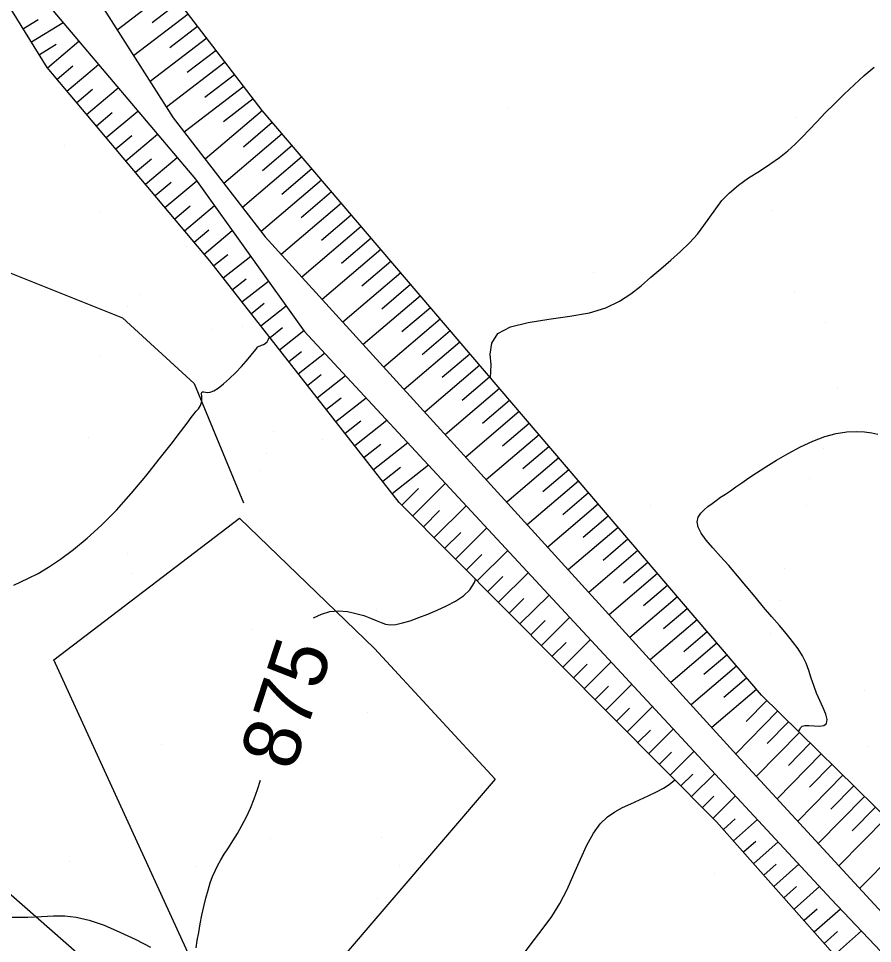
# Model space of a CAD drawing. Extents: x 400243 to 403697, y 4403637 to 4408083.
# Drawn here: x 402808 to 402920.2, y 4406336.6 to 4406458.2 of the extents above; entities that cross this region are included whole.
import ezdxf

# ---------------------------------------------------------------- set-up
doc = ezdxf.new("R2010")
doc.units = 0
doc.layers.add('HH_IC', color=7, linetype='Continuous')

msp = doc.modelspace()

# ---------------------------------------------------------------- linework, layer by layer
at = {"layer": 'HH_IC'}
for p, q in [((402840.01, 4406446.12), (402808.2, 4406487.63)), ((402811.77, 4406451.75), (402794.37, 4406479.94)), ((402808.28, 4406476.56), (402828.32, 4406445.14)), ((402809.29, 4406463.06), (402831.25, 4406437.09)), ((402827.85, 4406461.98), (402820.95, 4406456.69)), ((402825.55, 4406457.7), (402829.07, 4406460.39)), ((402830.29, 4406458.8), (402823.11, 4406453.31)), ((402810.58, 4406458.04), (402808.63, 4406456.84)), ((402809.68, 4406455.14), (402813.83, 4406457.7)), ((402827.85, 4406454.42), (402831.5, 4406457.22)), ((402812.93, 4406454.8), (402810.73, 4406453.44)), ((402811.78, 4406451.74), (402815.93, 4406455.22)), ((402832.72, 4406455.63), (402825.27, 4406449.92)), ((402830.14, 4406451.14), (402833.93, 4406454.04)), ((402814.35, 4406448.67), (402818.51, 4406452.16)), ((402835.15, 4406452.45), (402827.43, 4406446.54)), ((402811.77, 4406451.75), (402811.77, 4406451.75)), ((402833.1, 4406426.36), (402811.77, 4406451.75)), ((402815.14, 4406451.95), (402813.07, 4406450.21)), ((402832.45, 4406447.87), (402836.37, 4406450.87)), ((402817.72, 4406448.89), (402815.64, 4406447.14)), ((402816.93, 4406445.61), (402821.09, 4406449.11)), ((402837.58, 4406449.28), (402829.76, 4406443.28)), ((402828.13, 4406447.8), (402828.13, 4406447.8)), ((402834.89, 4406444.69), (402838.8, 4406447.69)), ((402819.5, 4406442.55), (402823.67, 4406446.05)), ((402840.02, 4406446.1), (402832.52, 4406439.71)), ((402840.01, 4406446.12), (402840.01, 4406446.12)), ((402905.56, 4406369.26), (402840.01, 4406446.12)), ((402872.17, 4406446.47), (402872.17, 4406446.47)), ((402820.3, 4406445.83), (402818.21, 4406444.08)), ((402828.32, 4406445.14), (402828.32, 4406445.14)), ((402828.32, 4406445.14), (402840.38, 4406429.52)), ((402910.22, 4406445.21), (402910.22, 4406445.21)), ((402837.53, 4406441.35), (402841.32, 4406444.58)), ((402822.88, 4406442.77), (402820.79, 4406441.02)), ((402822.07, 4406439.49), (402826.25, 4406443)), ((402842.61, 4406443.06), (402834.96, 4406436.54)), ((402814.08, 4406441.55), (402814.08, 4406441.55)), ((402840.05, 4406438.25), (402843.91, 4406441.54)), ((402845.21, 4406440.02), (402837.41, 4406433.37)), ((402825.45, 4406439.71), (402823.36, 4406437.96)), ((402824.65, 4406436.42), (402828.84, 4406439.95)), ((402842.57, 4406435.14), (402846.51, 4406438.5)), ((402828.03, 4406436.66), (402825.93, 4406434.89)), ((402827.22, 4406433.36), (402831.4, 4406436.88)), ((402831.25, 4406437.09), (402831.25, 4406437.09)), ((402831.25, 4406437.09), (402845.52, 4406417.11)), ((402847.8, 4406436.97), (402839.86, 4406430.2)), ((402845.13, 4406432.06), (402849.1, 4406435.45)), ((402829.98, 4406435.01), (402829.98, 4406435.01)), ((402850.4, 4406433.93), (402842.5, 4406427.19)), ((402818.57, 4406432.73), (402818.57, 4406432.73)), ((402830.54, 4406433.54), (402828.51, 4406431.83)), ((402829.79, 4406430.3), (402833.73, 4406433.61)), ((402906.83, 4406432.99), (402906.83, 4406432.99)), ((402847.77, 4406429.06), (402851.7, 4406432.41)), ((402832.99, 4406430.37), (402831.08, 4406428.77)), ((402832.37, 4406427.24), (402836.07, 4406430.35)), ((402853, 4406430.89), (402845.19, 4406424.23)), ((402840.38, 4406429.52), (402840.38, 4406429.52)), ((402840.38, 4406429.52), (402902.34, 4406361.38)), ((402850.41, 4406426.06), (402854.29, 4406429.37)), ((402830.08, 4406428.22), (402830.08, 4406428.22)), ((402855.59, 4406427.84), (402847.88, 4406421.27)), ((402835.48, 4406427.14), (402833.63, 4406425.69)), ((402834.86, 4406424.11), (402838.49, 4406426.96)), ((402802.71, 4406426.43), (402821.63, 4406418.88)), ((402833.1, 4406426.36), (402833.1, 4406426.36)), ((402857.99, 4406394.6), (402833.1, 4406426.36)), ((402853.06, 4406423.05), (402856.89, 4406426.32)), ((402858.19, 4406424.8), (402850.57, 4406418.31)), ((402883.51, 4406424.87), (402883.51, 4406424.87)), ((402837.88, 4406423.93), (402836.1, 4406422.54)), ((402837.33, 4406420.97), (402840.82, 4406423.7)), ((402855.7, 4406420.05), (402859.49, 4406423.28)), ((402823.83, 4406421.99), (402823.83, 4406421.99)), ((402860.78, 4406421.76), (402853.27, 4406415.35)), ((402909.94, 4406422.3), (402909.94, 4406422.3)), ((402840.27, 4406420.73), (402838.57, 4406419.39)), ((402822.3, 4406420.38), (402822.3, 4406420.38)), ((402839.8, 4406417.82), (402843.14, 4406420.44)), ((402858.35, 4406417.05), (402862.08, 4406420.23)), ((402821.63, 4406418.88), (402821.63, 4406418.88)), ((402821.63, 4406418.88), (402831.06, 4406410.25)), ((402863.38, 4406418.71), (402855.96, 4406412.39)), ((402913.96, 4406418.2), (402913.96, 4406418.2)), ((402833.5, 4406417.27), (402833.5, 4406417.27)), ((402837.46, 4406417.72), (402837.46, 4406417.72)), ((402842.67, 4406417.53), (402841.03, 4406416.24)), ((402842.27, 4406414.67), (402845.47, 4406417.18)), ((402845.52, 4406417.11), (402845.52, 4406417.11)), ((402845.52, 4406417.11), (402914.74, 4406342.46)), ((402860.99, 4406414.05), (402864.68, 4406417.19)), ((402865.97, 4406415.67), (402858.65, 4406409.43)), ((402818.57, 4406413.97), (402818.57, 4406413.97)), ((402845.16, 4406414.4), (402843.5, 4406413.09)), ((402844.73, 4406411.52), (402848.19, 4406414.23)), ((402863.64, 4406411.05), (402867.27, 4406414.15)), ((402868.57, 4406412.63), (402861.34, 4406406.46)), ((402847.76, 4406411.35), (402845.97, 4406409.95)), ((402847.2, 4406408.37), (402850.92, 4406411.29)), ((402866.28, 4406408.04), (402869.87, 4406411.1)), ((402831.06, 4406410.25), (402831.06, 4406410.25)), ((402831.06, 4406410.25), (402837.53, 4406394.53)), ((402871.17, 4406409.58), (402864.04, 4406403.5)), ((402915.61, 4406409.63), (402915.61, 4406409.63)), ((402849.67, 4406405.22), (402853.65, 4406408.34)), ((402850.36, 4406408.31), (402848.44, 4406406.8)), ((402868.92, 4406405.04), (402872.46, 4406408.06)), ((402831.16, 4406406.62), (402831.16, 4406406.62)), ((402873.76, 4406406.54), (402866.73, 4406400.54)), ((402852.96, 4406405.26), (402850.9, 4406403.65)), ((402852.14, 4406402.08), (402856.38, 4406405.4)), ((402871.57, 4406402.04), (402875.06, 4406405.02)), ((402841.52, 4406403.95), (402841.52, 4406403.95)), ((402876.36, 4406403.5), (402869.42, 4406397.58)), ((402817.17, 4406403.08), (402817.17, 4406403.08)), ((402847.94, 4406402.84), (402847.94, 4406402.84)), ((402854.6, 4406398.93), (402859.11, 4406402.46)), ((402855.56, 4406402.22), (402853.37, 4406400.5)), ((402874.21, 4406399.04), (402877.65, 4406401.97)), ((402913.76, 4406401.71), (402913.76, 4406401.71)), ((402840.56, 4406401.03), (402840.56, 4406401.03)), ((402878.95, 4406400.45), (402872.12, 4406394.62)), ((402839.82, 4406398.77), (402839.82, 4406398.77)), ((402858.16, 4406399.17), (402855.84, 4406397.35)), ((402857.07, 4406395.78), (402861.84, 4406399.52)), ((402876.86, 4406396.04), (402880.25, 4406398.93)), ((402881.55, 4406397.41), (402874.81, 4406391.66)), ((402911.88, 4406397.8), (402911.88, 4406397.8)), ((402860.53, 4406396.41), (402858.35, 4406394.24)), ((402859.76, 4406392.83), (402864.07, 4406397.11)), ((402879.5, 4406393.03), (402882.85, 4406395.89)), ((402837.53, 4406394.53), (402837.53, 4406394.53)), ((402857.99, 4406394.6), (402857.99, 4406394.6)), ((402899.67, 4406352.63), (402857.99, 4406394.6)), ((402862.58, 4406389.99), (402866.79, 4406394.17)), ((402884.14, 4406394.37), (402877.5, 4406388.7)), ((402890.97, 4406394.13), (402890.97, 4406394.13)), ((402911.46, 4406394.25), (402911.46, 4406394.25)), ((402863.3, 4406393.52), (402861.17, 4406391.41)), ((402882.14, 4406390.03), (402885.44, 4406392.84)), ((402812.62, 4406373.9), (402837.03, 4406392.51)), ((402837.03, 4406392.51), (402837.03, 4406392.51)), ((402837.03, 4406392.51), (402854.74, 4406375.41)), ((402886.74, 4406391.32), (402880.19, 4406385.74)), ((402866.07, 4406390.64), (402863.99, 4406388.57)), ((402865.4, 4406387.15), (402869.51, 4406391.24)), ((402884.79, 4406387.03), (402888.04, 4406389.8)), ((402822.33, 4406387.88), (402822.33, 4406387.88)), ((402868.84, 4406387.75), (402866.81, 4406385.73)), ((402868.21, 4406384.31), (402872.24, 4406388.3)), ((402889.33, 4406388.28), (402882.89, 4406382.78)), ((402887.43, 4406384.03), (402890.63, 4406386.76)), ((402822.85, 4406385.29), (402822.85, 4406385.29)), ((402871.03, 4406381.47), (402874.96, 4406385.37)), ((402891.93, 4406385.24), (402885.58, 4406379.82)), ((402908.55, 4406385.91), (402908.55, 4406385.91)), ((402871.61, 4406384.86), (402869.62, 4406382.89)), ((402890.08, 4406381.03), (402893.23, 4406383.71)), ((402874.38, 4406381.98), (402872.44, 4406380.05)), ((402873.85, 4406378.63), (402877.68, 4406382.43)), ((402894.53, 4406382.19), (402888.27, 4406376.86)), ((402907.98, 4406381.69), (402907.98, 4406381.69)), ((402855.03, 4406380.53), (402855.03, 4406380.53)), ((402892.72, 4406378.02), (402895.82, 4406380.67)), ((402876.67, 4406375.8), (402880.4, 4406379.5)), ((402838.62, 4406377.96), (402838.62, 4406377.96)), ((402877.15, 4406379.09), (402875.26, 4406377.21)), ((402897.12, 4406379.15), (402890.96, 4406373.9)), ((402895.37, 4406375.02), (402898.42, 4406377.63)), ((402906.77, 4406377.36), (402906.77, 4406377.36)), ((402879.92, 4406376.2), (402878.08, 4406374.38)), ((402879.49, 4406372.96), (402883.12, 4406376.56)), ((402899.72, 4406376.1), (402893.66, 4406370.94)), ((402854.74, 4406375.41), (402854.74, 4406375.41)), ((402854.74, 4406375.41), (402870.61, 4406358.24)), ((402898.01, 4406372.02), (402901.02, 4406374.58)), ((402812.62, 4406373.9), (402812.62, 4406373.9)), ((402832.11, 4406331.32), (402812.62, 4406373.9)), ((402882.69, 4406373.32), (402880.9, 4406371.54)), ((402882.31, 4406370.12), (402885.84, 4406373.63)), ((402902.31, 4406373.06), (402896.35, 4406367.98)), ((402885.12, 4406367.28), (402888.56, 4406370.69)), ((402900.65, 4406369.02), (402903.61, 4406371.54)), ((402885.46, 4406370.43), (402883.72, 4406368.7)), ((402904.91, 4406370.02), (402899.04, 4406365.01)), ((402919.07, 4406369.88), (402919.07, 4406369.88)), ((402903.56, 4406365.79), (402906.27, 4406368.56)), ((402905.56, 4406369.26), (402905.56, 4406369.26)), ((402937.32, 4406338.07), (402905.56, 4406369.26)), ((402888.23, 4406367.54), (402886.53, 4406365.86)), ((402887.94, 4406364.44), (402891.28, 4406367.76)), ((402907.7, 4406367.16), (402902.19, 4406361.55)), ((402853.89, 4406366.92), (402853.89, 4406366.92)), ((402839.8, 4406364.77), (402839.8, 4406364.77)), ((402891, 4406364.66), (402889.35, 4406363.02)), ((402890.76, 4406361.6), (402894.01, 4406364.82)), ((402906.34, 4406362.91), (402909.13, 4406365.75)), ((402910.55, 4406364.35), (402904.9, 4406358.6)), ((402826.81, 4406362.78), (402826.81, 4406362.78)), ((402909.12, 4406360.04), (402911.98, 4406362.95)), ((402919.53, 4406362.56), (402919.53, 4406362.56)), ((402893.77, 4406361.77), (402892.17, 4406360.18)), ((402893.58, 4406358.76), (402896.73, 4406361.89)), ((402902.34, 4406361.38), (402902.34, 4406361.38)), ((402902.34, 4406361.38), (402934.09, 4406326.86)), ((402913.41, 4406361.55), (402907.62, 4406355.65)), ((402911.9, 4406357.16), (402914.83, 4406360.15)), ((402896.54, 4406358.88), (402894.99, 4406357.35)), ((402896.4, 4406355.93), (402899.45, 4406358.95)), ((402916.26, 4406358.75), (402910.33, 4406352.7)), ((402817.62, 4406333.67), (402790.33, 4406357.62)), ((402870.61, 4406358.24), (402843.42, 4406326.49)), ((402870.61, 4406358.24), (402870.61, 4406358.24)), ((402914.69, 4406354.29), (402917.69, 4406357.35)), ((402899.31, 4406356), (402897.81, 4406354.51)), ((402899.22, 4406353.09), (402902.17, 4406356.02)), ((402919.12, 4406355.95), (402913.04, 4406349.76)), ((402917.47, 4406351.41), (402920.54, 4406354.54)), ((402899.67, 4406352.63), (402899.67, 4406352.63)), ((402933.83, 4406314.03), (402899.67, 4406352.63)), ((402902.13, 4406353), (402900.57, 4406351.61)), ((402901.89, 4406350.12), (402905.05, 4406352.91)), ((402921.97, 4406353.14), (402915.75, 4406346.81)), ((402915.34, 4406351.89), (402915.34, 4406351.89)), ((402841.09, 4406350.46), (402841.09, 4406350.46)), ((402855.69, 4406350.52), (402855.69, 4406350.52)), ((402904.82, 4406350.03), (402903.22, 4406348.62)), ((402904.55, 4406347.12), (402907.77, 4406349.98)), ((402924.82, 4406350.34), (402918.46, 4406343.86)), ((402814.7, 4406347.36), (402814.7, 4406347.36)), ((402831.36, 4406346.77), (402831.36, 4406346.77)), ((402858.07, 4406346.91), (402858.07, 4406346.91)), ((402907.5, 4406347.07), (402905.87, 4406345.62)), ((402907.2, 4406344.13), (402910.49, 4406347.04)), ((402860.59, 4406345.28), (402860.59, 4406345.28)), ((402899.38, 4406345.87), (402899.38, 4406345.87)), ((402910.19, 4406344.1), (402908.52, 4406342.63)), ((402909.85, 4406341.13), (402913.21, 4406344.11)), ((402855.19, 4406342.56), (402855.19, 4406342.56)), ((402914.74, 4406342.46), (402914.74, 4406342.46)), ((402914.74, 4406342.46), (402941.82, 4406313.88)), ((402912.87, 4406341.14), (402911.17, 4406339.63)), ((402912.5, 4406338.14), (402915.95, 4406341.19)), ((402915.57, 4406338.19), (402913.82, 4406336.64)), ((402915.15, 4406335.14), (402918.7, 4406338.28))]:
    msp.add_line(p, q, dxfattribs=at)
for points in [[(402870, 4406410.95), (402870.07, 4406412.69), (402869.95, 4406414.1), (402870.14, 4406415.54), (402870.96, 4406416.79), (402872.62, 4406417.67), (402874.94, 4406418.26), (402877.64, 4406418.69), (402880.41, 4406419.07), (402882.99, 4406419.54), (402885.14, 4406420.2), (402886.91, 4406421.04), (402888.41, 4406422.01), (402889.75, 4406423.08), (402891.03, 4406424.19), (402892.34, 4406425.32), (402893.65, 4406426.46), (402894.92, 4406427.6), (402896.1, 4406428.73), (402897.15, 4406429.87), (402898.02, 4406431), (402898.8, 4406432.11), (402899.56, 4406433.21), (402900.38, 4406434.28), (402901.36, 4406435.31), (402902.55, 4406436.3), (402903.89, 4406437.25), (402905.3, 4406438.16), (402906.68, 4406439.06), (402907.95, 4406439.93), (402909.05, 4406440.8), (402910.02, 4406441.68), (402910.93, 4406442.6), (402911.85, 4406443.58), (402912.83, 4406444.64), (402913.94, 4406445.79), (402915.15, 4406447.01), (402916.43, 4406448.26), (402917.74, 4406449.5), (402919.06, 4406450.7), (402920.36, 4406451.82)], [(402807.38, 4406383.74), (402808.27, 4406384.15), (402809.32, 4406384.65), (402810.55, 4406385.27), (402811.94, 4406386.09), (402813.5, 4406387.12), (402815.19, 4406388.39), (402817, 4406389.89), (402818.89, 4406391.63), (402820.84, 4406393.6), (402822.8, 4406395.79), (402824.71, 4406398.06), (402826.48, 4406400.27), (402828.02, 4406402.26), (402829.25, 4406403.88), (402830.12, 4406405.03), (402830.68, 4406405.76), (402831.01, 4406406.19), (402831.2, 4406406.43), (402831.33, 4406406.58), (402831.47, 4406406.74), (402831.62, 4406406.92), (402831.77, 4406407.12), (402831.9, 4406407.35), (402831.99, 4406407.6), (402832.05, 4406407.86), (402832.07, 4406408.13), (402832.06, 4406408.39), (402832.05, 4406408.63), (402832.03, 4406408.82), (402832.03, 4406408.97), (402832.05, 4406409.07), (402832.1, 4406409.13), (402832.19, 4406409.14), (402832.33, 4406409.12), (402832.53, 4406409.08), (402832.8, 4406409.06), (402833.17, 4406409.11), (402833.63, 4406409.29), (402834.22, 4406409.64), (402834.93, 4406410.2), (402835.71, 4406410.91), (402836.51, 4406411.7), (402837.26, 4406412.48), (402837.9, 4406413.18), (402838.38, 4406413.75), (402838.73, 4406414.18), (402838.98, 4406414.49), (402839.14, 4406414.72), (402839.27, 4406414.88), (402839.37, 4406415), (402839.48, 4406415.08), (402839.6, 4406415.14), (402839.74, 4406415.2), (402839.92, 4406415.27), (402840.15, 4406415.36), (402840.4, 4406415.49), (402840.64, 4406415.71), (402840.84, 4406416.04), (402840.94, 4406416.37)], [(402910.42, 4406364.48), (402910.6, 4406364.77), (402910.71, 4406364.98), (402910.9, 4406365.17), (402911.25, 4406365.27), (402911.81, 4406365.27), (402912.49, 4406365.23), (402913.18, 4406365.21), (402913.76, 4406365.29), (402914.12, 4406365.55), (402914.19, 4406366.05), (402914.01, 4406366.75), (402913.66, 4406367.6), (402913.23, 4406368.55), (402912.8, 4406369.54), (402912.44, 4406370.54), (402912.12, 4406371.52), (402911.8, 4406372.5), (402911.43, 4406373.46), (402910.97, 4406374.42), (402910.38, 4406375.36), (402909.67, 4406376.32), (402908.85, 4406377.33), (402907.94, 4406378.4), (402906.93, 4406379.57), (402905.86, 4406380.85), (402904.73, 4406382.21), (402903.58, 4406383.6), (402902.42, 4406384.97), (402901.27, 4406386.29), (402900.17, 4406387.51), (402899.17, 4406388.63), (402898.31, 4406389.64), (402897.66, 4406390.54), (402897.25, 4406391.34), (402897.14, 4406392.04), (402897.27, 4406392.64), (402897.59, 4406393.17), (402898.03, 4406393.64), (402898.55, 4406394.07), (402899.08, 4406394.47), (402899.63, 4406394.87), (402900.21, 4406395.27), (402900.83, 4406395.69), (402901.49, 4406396.14), (402902.2, 4406396.64), (402902.99, 4406397.19), (402903.9, 4406397.82), (402904.94, 4406398.51), (402906.15, 4406399.29), (402907.55, 4406400.15), (402909.08, 4406401.04), (402910.69, 4406401.89), (402912.32, 4406402.65), (402913.9, 4406403.25), (402915.4, 4406403.65), (402916.77, 4406403.86), (402918.01, 4406403.92), (402919.12, 4406403.86), (402920.06, 4406403.73), (402920.86, 4406403.56)], [(402846.73, 4406379.42), (402847.77, 4406379.92), (402848.88, 4406380.24), (402850.03, 4406380.34), (402851.19, 4406380.25), (402852.3, 4406380.02), (402853.33, 4406379.72), (402854.23, 4406379.38), (402854.97, 4406379.06), (402855.6, 4406378.8), (402856.2, 4406378.61), (402856.82, 4406378.52), (402857.55, 4406378.56), (402858.42, 4406378.75), (402859.43, 4406379.05), (402860.55, 4406379.46), (402861.74, 4406379.93), (402862.97, 4406380.45), (402864.2, 4406381), (402865.37, 4406381.61), (402866.42, 4406382.3), (402867.28, 4406383.11), (402867.89, 4406384.08), (402868.01, 4406384.52)], [(402831.32, 4406336.05), (402831.47, 4406337.02), (402831.65, 4406338.08), (402831.85, 4406339.2), (402832.07, 4406340.35), (402832.33, 4406341.49), (402832.6, 4406342.59), (402832.88, 4406343.64), (402833.17, 4406344.59), (402833.48, 4406345.43), (402833.8, 4406346.19), (402834.16, 4406346.9), (402834.56, 4406347.62), (402835.02, 4406348.38), (402835.55, 4406349.21), (402836.13, 4406350.12), (402836.74, 4406351.1), (402837.34, 4406352.14), (402837.92, 4406353.25), (402838.45, 4406354.42), (402838.94, 4406355.63), (402839.37, 4406356.85), (402839.77, 4406358.08)], [(402874.55, 4406335.54), (402875.75, 4406337.14), (402876.91, 4406338.65), (402878.03, 4406340.19), (402879.07, 4406341.86), (402880.03, 4406343.73), (402880.93, 4406345.73), (402881.79, 4406347.71), (402882.64, 4406349.55), (402883.5, 4406351.12), (402884.4, 4406352.34), (402885.33, 4406353.25), (402886.31, 4406353.94), (402887.34, 4406354.49), (402888.43, 4406354.99), (402889.57, 4406355.51), (402890.71, 4406356.04), (402891.77, 4406356.57), (402892.71, 4406357.06), (402893.43, 4406357.52), (402893.93, 4406357.9), (402894.21, 4406358.13)], [(402807.17, 4406340.06), (402809.23, 4406340.1), (402811, 4406340.19), (402812.57, 4406340.27), (402814.06, 4406340.26), (402815.58, 4406340.1), (402817.28, 4406339.7), (402819.22, 4406339.01), (402821.3, 4406338.12), (402823.39, 4406337.13), (402825.34, 4406336.14)]]:
    msp.add_lwpolyline(points, dxfattribs=at)

# ---------------------------------------------------------------- texts
msp.add_text('875', height=7.5, rotation=71.9287, dxfattribs=at).set_placement((402844.05, 4406359.12))

doc.saveas('drawing.dxf')
